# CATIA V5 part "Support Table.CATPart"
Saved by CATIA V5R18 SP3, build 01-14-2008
Part number: Moving Part Rail Guide
Bounding box of the stored display mesh (mm): x -33 to 33, y -38.455 to 38, z -0.893 to 18.591
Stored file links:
  E:\#00 CATIA V5 Movie\#03 CATIA V5 Data\#07 KIN\Balance Unit (1)\Support Table.CATPart
  CATDrawing1.CATDrawing
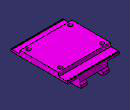
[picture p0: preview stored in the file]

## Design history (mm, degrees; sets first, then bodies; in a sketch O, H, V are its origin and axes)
Body1 "PartBody" (main body)
  Solid1: solid without history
